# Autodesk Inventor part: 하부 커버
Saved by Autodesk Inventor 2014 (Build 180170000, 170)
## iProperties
Created: 2026-08
Part Number: 하부 커버
Material: 일반
Document SubType Name: Modeling
Designer: dg
Density: 1 g/cm^3
Appearance: 기본값
Author: dg
Author: jhkim
Creation Date: 2026-07-31
Sending System: Autodesk Inventor 2027
Preprocessor: ST-DEVELOPER v20.1
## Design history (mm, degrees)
node "하부 커버1"
node "솔리드1"
node "기준1"
